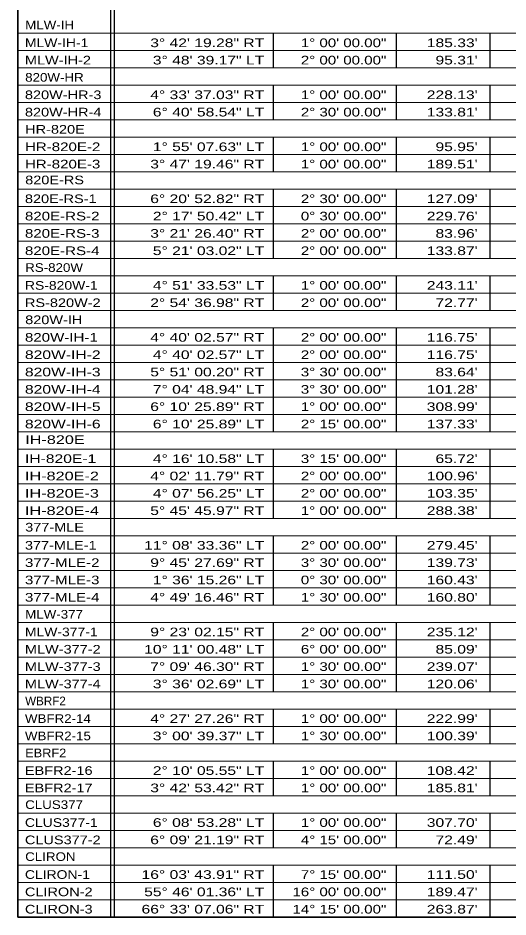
# Model space of a CAD drawing. Extents: x 1953053 to 1967065, y 7363860 to 7371201.
# Drawn here: x 1959957 to 1960635, y 7368112 to 7369357 of the extents above; entities that cross this region are included whole.
import ezdxf
from ezdxf.enums import TextEntityAlignment as Align

# ---------------------------------------------------------------- set-up
doc = ezdxf.new("R2010")
doc.units = 0
doc.header["$LTSCALE"] = 4.8
doc.layers.add('10', color=7, linetype='Continuous')
doc.layers.add('12', color=7, linetype='Continuous', lineweight=25)

msp = doc.modelspace()

# ---------------------------------------------------------------- linework, layer by layer
at = {"layer": '12', "lineweight": 35}
for p, q in [((1959956.881, 7370164.879), (1959956.881, 7368111.747)), ((1959956.881, 7368111.747), (1961680.213, 7368111.747))]:
    msp.add_line(p, q, dxfattribs=at)
at = {"layer": '12'}
for p, q in [((1960084.726, 7370136.079), (1960084.726, 7368111.747)), ((1960090.213, 7370136.079), (1960090.213, 7368111.747)), ((1960310.213, 7369335.746), (1960310.213, 7369287.746)), ((1960480.213, 7369335.746), (1960480.213, 7369287.746)), ((1960610.213, 7369335.746), (1960610.213, 7369287.746)), ((1960310.213, 7369263.746), (1960310.213, 7369215.746)), ((1960480.213, 7369263.746), (1960480.213, 7369215.746)), ((1960610.213, 7369263.746), (1960610.213, 7369215.746)), ((1960310.213, 7369191.746), (1960310.213, 7369143.746)), ((1960480.213, 7369191.746), (1960480.213, 7369143.746)), ((1960610.213, 7369191.746), (1960610.213, 7369143.746)), ((1960310.213, 7369119.746), (1960310.213, 7369023.746)), ((1960480.213, 7369119.746), (1960480.213, 7369023.746)), ((1960610.213, 7369119.746), (1960610.213, 7369023.746)), ((1960310.213, 7368999.746), (1960310.213, 7368951.746)), ((1960480.213, 7368999.746), (1960480.213, 7368951.746)), ((1960610.213, 7368999.746), (1960610.213, 7368951.746)), ((1960310.213, 7368927.746), (1960310.213, 7368783.747)), ((1960480.213, 7368927.746), (1960480.213, 7368783.747)), ((1960610.213, 7368927.746), (1960610.213, 7368783.747)), ((1960310.213, 7368759.747), (1960310.213, 7368663.747)), ((1960480.213, 7368759.747), (1960480.213, 7368663.747)), ((1960610.213, 7368759.747), (1960610.213, 7368663.747)), ((1960310.213, 7368639.747), (1960310.213, 7368543.747)), ((1960480.213, 7368639.747), (1960480.213, 7368543.747)), ((1960610.213, 7368639.747), (1960610.213, 7368543.747)), ((1960310.213, 7368519.747), (1960310.213, 7368423.747)), ((1960480.213, 7368519.747), (1960480.213, 7368423.747)), ((1960610.213, 7368519.747), (1960610.213, 7368423.747)), ((1960310.213, 7368399.747), (1960310.213, 7368351.747)), ((1960480.213, 7368399.747), (1960480.213, 7368351.747)), ((1960610.213, 7368399.747), (1960610.213, 7368351.747)), ((1960310.213, 7368327.747), (1960310.213, 7368279.747)), ((1960480.213, 7368327.747), (1960480.213, 7368279.747)), ((1960610.213, 7368327.747), (1960610.213, 7368279.747)), ((1960310.213, 7368255.747), (1960310.213, 7368207.747)), ((1960480.213, 7368255.747), (1960480.213, 7368207.747)), ((1960610.213, 7368255.747), (1960610.213, 7368207.747)), ((1960310.213, 7368183.747), (1960310.213, 7368111.747)), ((1960480.213, 7368183.747), (1960480.213, 7368111.747)), ((1960610.213, 7368183.747), (1960610.213, 7368111.747))]:
    msp.add_line(p, q, dxfattribs=at)
at = {"layer": '12', "lineweight": 13}
for p, q in [((1959956.881, 7369335.746), (1961680.213, 7369335.746)), ((1959956.881, 7369311.746), (1961680.213, 7369311.746)), ((1959956.881, 7369287.746), (1961680.213, 7369287.746)), ((1959956.881, 7369263.746), (1961680.213, 7369263.746)), ((1959956.881, 7369239.746), (1961680.213, 7369239.746)), ((1959956.881, 7369215.746), (1961680.213, 7369215.746)), ((1959956.881, 7369191.746), (1961680.213, 7369191.746)), ((1959956.881, 7369167.746), (1961680.213, 7369167.746)), ((1959956.881, 7369143.746), (1961680.213, 7369143.746)), ((1959956.881, 7369119.746), (1961680.213, 7369119.746)), ((1959956.881, 7369095.746), (1961680.213, 7369095.746)), ((1959956.881, 7369071.746), (1961680.213, 7369071.746)), ((1959956.881, 7369047.746), (1961680.213, 7369047.746)), ((1959956.881, 7369023.746), (1961680.213, 7369023.746)), ((1959956.881, 7368999.746), (1961680.213, 7368999.746)), ((1959956.881, 7368975.746), (1961680.213, 7368975.746)), ((1959956.881, 7368951.746), (1961680.213, 7368951.746)), ((1959956.881, 7368927.746), (1961680.213, 7368927.746)), ((1959956.881, 7368903.746), (1961680.213, 7368903.746)), ((1959956.881, 7368879.746), (1961680.213, 7368879.746)), ((1959956.881, 7368855.746), (1961680.213, 7368855.746)), ((1959956.881, 7368831.747), (1961680.213, 7368831.747)), ((1959956.881, 7368807.747), (1961680.213, 7368807.747)), ((1959956.881, 7368783.747), (1961680.213, 7368783.747)), ((1959956.881, 7368759.747), (1961680.213, 7368759.747)), ((1959956.881, 7368735.747), (1961680.213, 7368735.747)), ((1959956.881, 7368711.747), (1961680.213, 7368711.747)), ((1959956.881, 7368687.747), (1961680.213, 7368687.747)), ((1959956.881, 7368663.747), (1961680.213, 7368663.747)), ((1959956.881, 7368639.747), (1961680.213, 7368639.747)), ((1959956.881, 7368615.747), (1961680.213, 7368615.747)), ((1959956.881, 7368591.747), (1961680.213, 7368591.747)), ((1959956.881, 7368567.747), (1961680.213, 7368567.747)), ((1959956.881, 7368543.747), (1961680.213, 7368543.747)), ((1959956.881, 7368519.747), (1961680.213, 7368519.747)), ((1959956.881, 7368495.747), (1961680.213, 7368495.747)), ((1959956.881, 7368471.747), (1961680.213, 7368471.747)), ((1959956.881, 7368447.747), (1961680.213, 7368447.747)), ((1959956.881, 7368423.747), (1961680.213, 7368423.747)), ((1959956.881, 7368399.747), (1961680.213, 7368399.747)), ((1959956.881, 7368375.747), (1961680.213, 7368375.747)), ((1959956.881, 7368351.747), (1961680.213, 7368351.747)), ((1959956.881, 7368327.747), (1961680.213, 7368327.747)), ((1959956.881, 7368303.747), (1961680.213, 7368303.747)), ((1959956.881, 7368279.747), (1961680.213, 7368279.747)), ((1959956.881, 7368255.747), (1961680.213, 7368255.747)), ((1959956.881, 7368231.747), (1961680.213, 7368231.747)), ((1959956.881, 7368207.747), (1961680.213, 7368207.747)), ((1959956.881, 7368207.747), (1961680.213, 7368207.747)), ((1959956.881, 7368183.747), (1961680.213, 7368183.747)), ((1959956.881, 7368183.747), (1961680.213, 7368183.747)), ((1959956.881, 7368159.747), (1961680.213, 7368159.747)), ((1959956.881, 7368135.747), (1961680.213, 7368135.747)), ((1959956.881, 7368111.747), (1961680.213, 7368111.747))]:
    msp.add_line(p, q, dxfattribs=at)

# ---------------------------------------------------------------- texts
at = {"layer": '10'}
for s, width, p in [('MLW-IH', 1.15, (1959966.827, 7369341.291)), ('MLW-IH-1', 1.2, (1959966.502, 7369316.573)), ('MLW-IH-2', 1.25, (1959966.502, 7369292.573)), ('820W-HR', 1.15, (1959966.828, 7369268.704)), ('820W-HR-3', 1.25, (1959966.504, 7369244.572)), ('820W-HR-4', 1.25, (1959966.504, 7369220.572)), ('HR-820E', 1.25, (1959966.828, 7369196.715)), ('HR-820E-2', 1.3, (1959966.504, 7369172.572)), ('HR-820E-3', 1.3, (1959966.504, 7369148.572)), ('820E-RS', 1.25, (1959966.826, 7369126.604)), ('820E-RS-1', 1.25, (1959966.502, 7369100.573)), ('820E-RS-2', 1.3, (1959966.502, 7369076.573)), ('820E-RS-3', 1.3, (1959966.502, 7369052.573)), ('820E-RS-4', 1.3, (1959966.502, 7369028.573)), ('RS-820W', 1.15, (1959966.826, 7369005.292)), ('RS-820W-1', 1.2, (1959966.502, 7368980.573)), ('RS-820W-2', 1.25, (1959966.502, 7368956.573)), ('820W-IH', 1.25, (1959966.826, 7368932.931)), ('820W-IH-1', 1.3, (1959966.502, 7368908.573)), ('820W-IH-2', 1.35, (1959966.502, 7368884.573)), ('820W-IH-3', 1.35, (1959966.502, 7368860.573)), ('820W-IH-4', 1.35, (1959966.502, 7368836.573)), ('820W-IH-5', 1.35, (1959966.502, 7368812.573)), ('820W-IH-6', 1.35, (1959966.502, 7368788.573)), ('IH-820E', 1.4, (1959966.826, 7368766.925)), ('IH-820E-1', 1.35, (1959966.502, 7368740.574)), ('IH-820E-2', 1.4, (1959966.502, 7368716.574)), ('IH-820E-3', 1.4, (1959966.502, 7368692.574)), ('IH-820E-4', 1.4, (1959966.502, 7368668.574)), ('377-MLE', 1.25, (1959966.826, 7368645.667)), ('377-MLE-1', 1.25, (1959966.502, 7368620.574)), ('377-MLE-2', 1.3, (1959966.502, 7368596.574)), ('377-MLE-3', 1.3, (1959966.502, 7368572.574)), ('377-MLE-4', 1.3, (1959966.502, 7368548.574)), ('MLW-377', 1.15, (1959966.826, 7368525.015)), ('MLW-377-1', 1.2, (1959966.502, 7368500.574)), ('MLW-377-2', 1.25, (1959966.502, 7368476.574)), ('MLW-377-3', 1.25, (1959966.502, 7368452.574)), ('MLW-377-4', 1.25, (1959966.502, 7368428.574)), ('WBFR2-14', 1.15, (1959966.502, 7368380.574)), ('WBFR2-15', 1.15, (1959966.502, 7368356.574)), ('EBRF2', 1.1, (1959966.826, 7368333.015)), ('EBFR2-16', 1.25, (1959966.502, 7368308.574)), ('EBFR2-17', 1.25, (1959966.502, 7368284.574)), ('CLUS377', 1.15, (1959966.826, 7368261.361)), ('CLUS377-1', 1.2, (1959966.502, 7368236.574)), ('CLUS377-2', 1.25, (1959966.502, 7368212.574)), ('CLIRON', 1.15, (1959966.826, 7368189.361)), ('CLIRON-1', 1.2, (1959966.502, 7368164.574)), ('CLIRON-2', 1.25, (1959966.502, 7368140.574)), ('CLIRON-3', 1.25, (1959966.502, 7368116.574))]:
    msp.add_text(s, height=12, dxfattribs=dict(at, width=width)).set_placement(p)
for s, width, p in [('3° 42\' 19.28" RT', 1.35, (1960297.735, 7369316.573)), ('1° 00\' 00.00"', 1.3, (1960466.73, 7369316.573)), ("185.33'", 1.35, (1960593.14, 7369316.573)), ('3° 48\' 39.17" LT', 1.35, (1960297.735, 7369292.573)), ('2° 00\' 00.00"', 1.3, (1960466.73, 7369292.573)), ("95.31'", 1.35, (1960593.14, 7369292.573)), ('4° 33\' 37.03" RT', 1.35, (1960297.737, 7369244.572)), ('1° 00\' 00.00"', 1.3, (1960466.732, 7369244.572)), ("228.13'", 1.35, (1960593.142, 7369244.572)), ('6° 40\' 58.54" LT', 1.35, (1960297.737, 7369220.572)), ('2° 30\' 00.00"', 1.3, (1960466.732, 7369220.572)), ("133.81'", 1.35, (1960593.142, 7369220.572)), ('1° 55\' 07.63" LT', 1.35, (1960297.737, 7369172.572)), ('1° 00\' 00.00"', 1.3, (1960466.732, 7369172.572)), ("95.95'", 1.35, (1960593.142, 7369172.572)), ('3° 47\' 19.46" RT', 1.35, (1960297.737, 7369148.572)), ('1° 00\' 00.00"', 1.3, (1960466.732, 7369148.572)), ("189.51'", 1.35, (1960593.142, 7369148.572)), ('6° 20\' 52.82" RT', 1.35, (1960297.735, 7369100.573)), ('2° 30\' 00.00"', 1.3, (1960466.73, 7369100.573)), ("127.09'", 1.35, (1960593.14, 7369100.573)), ('2° 17\' 50.42" LT', 1.35, (1960297.735, 7369076.573)), ('0° 30\' 00.00"', 1.3, (1960466.73, 7369076.573)), ("229.76'", 1.35, (1960593.14, 7369076.573)), ('3° 21\' 26.40" RT', 1.35, (1960297.735, 7369052.573)), ('2° 00\' 00.00"', 1.3, (1960466.73, 7369052.573)), ("83.96'", 1.35, (1960593.14, 7369052.573)), ('5° 21\' 03.02" LT', 1.35, (1960297.735, 7369028.573)), ('2° 00\' 00.00"', 1.3, (1960466.73, 7369028.573)), ("133.87'", 1.35, (1960593.14, 7369028.573)), ('4° 51\' 33.53" LT', 1.35, (1960297.735, 7368980.573)), ('1° 00\' 00.00"', 1.3, (1960466.73, 7368980.573)), ("243.11'", 1.35, (1960593.14, 7368980.573)), ('2° 54\' 36.98" RT', 1.35, (1960297.735, 7368956.573)), ('2° 00\' 00.00"', 1.3, (1960466.73, 7368956.573)), ("72.77'", 1.35, (1960593.14, 7368956.573)), ('4° 40\' 02.57" RT', 1.35, (1960297.735, 7368908.573)), ('2° 00\' 00.00"', 1.3, (1960466.73, 7368908.573)), ("116.75'", 1.35, (1960593.14, 7368908.573)), ('4° 40\' 02.57" LT', 1.35, (1960297.735, 7368884.573)), ('2° 00\' 00.00"', 1.3, (1960466.73, 7368884.573)), ("116.75'", 1.35, (1960593.14, 7368884.573)), ('5° 51\' 00.20" RT', 1.35, (1960297.735, 7368860.573)), ('3° 30\' 00.00"', 1.3, (1960466.73, 7368860.573)), ("83.64'", 1.35, (1960593.14, 7368860.573)), ('7° 04\' 48.94" LT', 1.35, (1960297.735, 7368836.573)), ('3° 30\' 00.00"', 1.3, (1960466.73, 7368836.573)), ("101.28'", 1.35, (1960593.14, 7368836.573)), ('6° 10\' 25.89" RT', 1.35, (1960297.735, 7368812.573)), ('1° 00\' 00.00"', 1.3, (1960466.73, 7368812.573)), ("308.99'", 1.35, (1960593.14, 7368812.573)), ('6° 10\' 25.89" LT', 1.35, (1960297.735, 7368788.573)), ('2° 15\' 00.00"', 1.3, (1960466.73, 7368788.573)), ("137.33'", 1.35, (1960593.14, 7368788.573)), ('4° 16\' 10.58" LT', 1.35, (1960297.735, 7368740.574)), ('3° 15\' 00.00"', 1.3, (1960466.73, 7368740.574)), ("65.72'", 1.35, (1960593.14, 7368740.574)), ('4° 02\' 11.79" RT', 1.35, (1960297.735, 7368716.574)), ('2° 00\' 00.00"', 1.3, (1960466.73, 7368716.574)), ("100.96'", 1.35, (1960593.14, 7368716.574)), ('4° 07\' 56.25" LT', 1.35, (1960297.735, 7368692.574)), ('2° 00\' 00.00"', 1.3, (1960466.73, 7368692.574)), ("103.35'", 1.35, (1960593.14, 7368692.574)), ('5° 45\' 45.97" RT', 1.35, (1960297.735, 7368668.574)), ('1° 00\' 00.00"', 1.3, (1960466.73, 7368668.574)), ("288.38'", 1.35, (1960593.14, 7368668.574)), ('11° 08\' 33.36" LT', 1.35, (1960297.735, 7368620.574)), ('2° 00\' 00.00"', 1.3, (1960466.73, 7368620.574)), ("279.45'", 1.35, (1960593.14, 7368620.574)), ('9° 45\' 27.69" RT', 1.35, (1960297.735, 7368596.574)), ('3° 30\' 00.00"', 1.3, (1960466.73, 7368596.574)), ("139.73'", 1.35, (1960593.14, 7368596.574)), ('1° 36\' 15.26" LT', 1.35, (1960297.735, 7368572.574)), ('0° 30\' 00.00"', 1.3, (1960466.73, 7368572.574)), ("160.43'", 1.35, (1960593.14, 7368572.574)), ('4° 49\' 16.46" RT', 1.35, (1960297.735, 7368548.574)), ('1° 30\' 00.00"', 1.3, (1960466.73, 7368548.574)), ("160.80'", 1.35, (1960593.14, 7368548.574)), ('9° 23\' 02.15" RT', 1.35, (1960297.735, 7368500.574)), ('2° 00\' 00.00"', 1.3, (1960466.73, 7368500.574)), ("235.12'", 1.35, (1960593.14, 7368500.574)), ('10° 11\' 00.48" LT', 1.35, (1960297.735, 7368476.574)), ('6° 00\' 00.00"', 1.3, (1960466.73, 7368476.574)), ("85.09'", 1.35, (1960593.14, 7368476.574)), ('7° 09\' 46.30" RT', 1.35, (1960297.735, 7368452.574)), ('1° 30\' 00.00"', 1.3, (1960466.73, 7368452.574)), ("239.07'", 1.35, (1960593.14, 7368452.574)), ('3° 36\' 02.69" LT', 1.35, (1960297.735, 7368428.574)), ('1° 30\' 00.00"', 1.3, (1960466.73, 7368428.574)), ("120.06'", 1.35, (1960593.14, 7368428.574)), ('4° 27\' 27.26" RT', 1.35, (1960297.735, 7368380.574)), ('1° 00\' 00.00"', 1.3, (1960466.73, 7368380.574)), ("222.99'", 1.35, (1960593.14, 7368380.574)), ('3° 00\' 39.37" LT', 1.35, (1960297.735, 7368356.574)), ('1° 30\' 00.00"', 1.3, (1960466.73, 7368356.574)), ("100.39'", 1.35, (1960593.14, 7368356.574)), ('2° 10\' 05.55" LT', 1.35, (1960297.735, 7368308.574)), ('1° 00\' 00.00"', 1.3, (1960466.73, 7368308.574)), ("108.42'", 1.35, (1960593.14, 7368308.574)), ('3° 42\' 53.42" RT', 1.35, (1960297.735, 7368284.574)), ('1° 00\' 00.00"', 1.3, (1960466.73, 7368284.574)), ("185.81'", 1.35, (1960593.14, 7368284.574)), ('6° 08\' 53.28" LT', 1.35, (1960297.735, 7368236.574)), ('1° 00\' 00.00"', 1.3, (1960466.73, 7368236.574)), ("307.70'", 1.35, (1960593.14, 7368236.574)), ('6° 09\' 21.19" RT', 1.35, (1960297.735, 7368212.574)), ('4° 15\' 00.00"', 1.3, (1960466.73, 7368212.574)), ("72.49'", 1.35, (1960593.14, 7368212.574)), ('16° 03\' 43.91" RT', 1.35, (1960297.735, 7368164.574)), ('7° 15\' 00.00"', 1.3, (1960466.73, 7368164.574)), ("111.50'", 1.35, (1960593.14, 7368164.574)), ('55° 46\' 01.36" LT', 1.35, (1960297.735, 7368140.574)), ('16° 00\' 00.00"', 1.3, (1960466.73, 7368140.574)), ("189.47'", 1.35, (1960593.14, 7368140.574)), ('66° 33\' 07.06" RT', 1.35, (1960297.735, 7368116.574)), ('14° 15\' 00.00"', 1.3, (1960466.73, 7368116.574)), ("263.87'", 1.35, (1960593.14, 7368116.574))]:
    msp.add_text(s, height=12, dxfattribs=dict(at, width=width)).set_placement(p, align=Align.RIGHT)
msp.add_text('WBRF2', height=12, dxfattribs=at).set_placement((1959966.826, 7368405.015))

doc.saveas('drawing.dxf')
